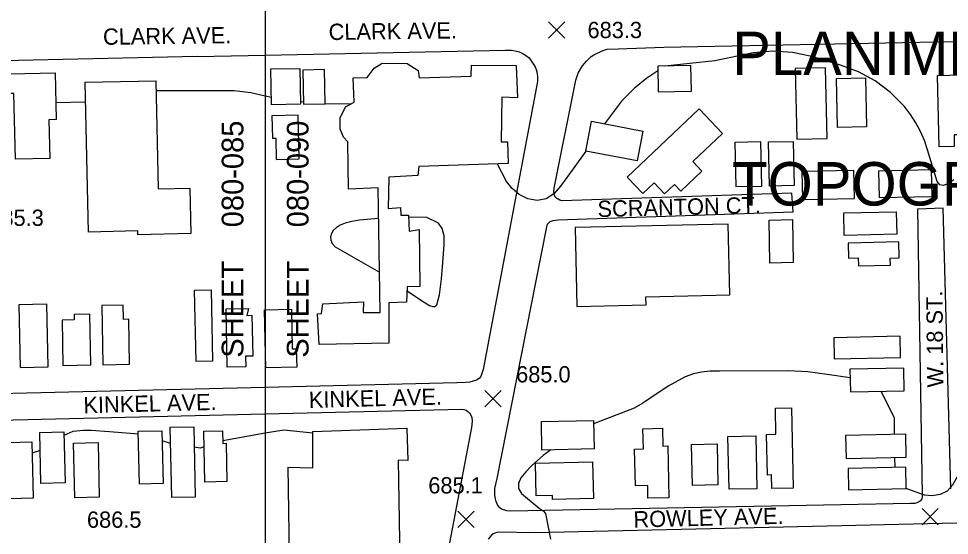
# Model space of a CAD drawing. Extents: x 79600 to 91800, y 75600 to 84400.
# Drawn here: x 84773 to 85630, y 78237 to 78712 of the extents above; entities that cross this region are included whole.
import ezdxf

# ---------------------------------------------------------------- set-up
doc = ezdxf.new("R2010")
doc.units = 0
for name, color, linetype in [('080-085$0$BLDG', 7, 'Continuous'), ('080-085$0$GRID', 7, 'Continuous'), ('080-085$0$INTER', 7, 'Continuous'), ('080-085$0$ROAD', 7, 'Continuous'), ('080-085$0$ROAD-NAME', 7, 'Continuous'), ('080-085$0$SPOTS', 7, 'Continuous'), ('080-085$0$TI_PLAN', 7, 'Continuous'), ('080-085$0$TI_SHEET', 7, 'Continuous'), ('080-085$0$TI_TOPO', 7, 'Continuous'), ('080-090$0$BLDG', 7, 'Continuous'), ('080-090$0$GRID', 7, 'Continuous'), ('080-090$0$INTER', 7, 'Continuous'), ('080-090$0$ROAD', 7, 'Continuous'), ('080-090$0$ROAD-NAME', 7, 'Continuous'), ('080-090$0$SPOTMARK', 7, 'Continuous'), ('080-090$0$SPOTS', 7, 'Continuous'), ('080-090$0$TI_SHEET', 7, 'Continuous')]:
    doc.layers.add(name, color=color, linetype=linetype)

# ---------------------------------------------------------------- blocks, each defined once
blk = doc.blocks.new('080-090$0$SPOTS')
at = {"layer": '080-090$0$SPOTMARK'}
for p, q in [((-0.5, -0.5), (0.5, 0.5)), ((-0.5, 0.5), (0.5, -0.5))]:
    blk.add_line(p, q, dxfattribs=at)

msp = doc.modelspace()

# ---------------------------------------------------------------- linework, layer by layer
at = {"layer": '080-085$0$BLDG'}
for p, q in [((84999.42, 78444.03), (85000, 78444.04)), ((85000, 78416.56), (84999.42, 78444.03))]:
    msp.add_line(p, q, dxfattribs=at)
for points in [[(84800.93, 78618.92), (84801.69, 78583.4), (84770, 78582.73), (84768.72, 78643.1), (84765.23, 78643.02), (84764.84, 78661.21), (84806.72, 78662.09), (84807.63, 78619.06)], [(84899.48, 78654.82), (84901.59, 78555.47), (84930.58, 78556.08), (84931.47, 78514.14), (84882.92, 78513.11), (84882.84, 78516.6), (84837.22, 78515.63), (84834.3, 78653.44)], [(84936.47, 78396.45), (84935.08, 78462.21), (84950.29, 78462.53), (84951.68, 78396.77)], [(84773.27, 78448.6), (84774.49, 78390.97), (84800.14, 78391.51), (84798.92, 78449.14)], [(84874.38, 78435.37), (84869.56, 78435.27), (84869.28, 78448.38), (84849.53, 78447.96), (84850.69, 78393.52), (84875.25, 78394.04)], [(84983.05, 78438.97), (84987.86, 78439.07), (84988.65, 78401.57), (84981.89, 78401.43), (84982.1, 78391.56), (84965.15, 78391.2), (84964.01, 78444.97), (84984.69, 78445.41)], [(84824.15, 78439.71), (84824.25, 78434.79), (84812.95, 78434.55), (84813.83, 78392.87), (84839.64, 78393.42), (84838.65, 78440.02)], [(84793.47, 78284.37), (84792.39, 78331.19), (84814.68, 78331.71), (84815.77, 78284.88)], [(84884.34, 78283.68), (84883.22, 78332.32), (84904.9, 78332.82), (84906.03, 78284.19)], [(84935.7, 78271.82), (84913.94, 78271.32), (84912.44, 78336.01), (84934.2, 78336.51)], [(84960.99, 78321.19), (84963.97, 78321.26), (84964.79, 78286.03), (84944.55, 78285.56), (84943.46, 78332.41), (84960.72, 78332.81)], [(84764.24, 78270.22), (84763.04, 78322.07), (84785.17, 78322.58), (84786.37, 78270.73)], [(84824.7, 78271.08), (84823.53, 78321.41), (84846.1, 78321.93), (84847.27, 78271.61)]]:
    msp.add_lwpolyline(points, close=True, dxfattribs=at)
at = {"layer": '080-085$0$GRID'}
msp.add_line((85000, 80000), (85000, 76000), dxfattribs=at)
at = {"layer": '080-085$0$INTER'}
for p, q in [((84834.69, 78635.03), (84807.3, 78634.5)), ((84912.79, 78321.17), (84905.12, 78323.52)), ((85000, 78330.72), (84960.94, 78323.43)), ((84792.77, 78314.53), (84785.41, 78312.08))]:
    msp.add_line(p, q, dxfattribs=at)
for points in [[(85000, 78640.69), (84986.98, 78643.63), (84971.62, 78645.59), (84899.68, 78645.49)], [(84883.28, 78329.77), (84856.68, 78331.78), (84839.69, 78332.97), (84832.62, 78333.12), (84823.06, 78332.05), (84814.76, 78328.39)], [(84943.8, 78317.91), (84940.04, 78316.7), (84934.64, 78317.59)]]:
    msp.add_lwpolyline(points, dxfattribs=at)
at = {"layer": '080-085$0$ROAD'}
msp.add_line((84937.29, 78676.99), (85000, 78678.32), dxfattribs=at)
for points in [[(85000, 78372.63), (84521.84, 78361.26), (84519.9, 78361.29), (84517.42, 78361.88), (84515.09, 78363.3), (84513.73, 78364.99), (84512.92, 78366.66), (84512.72, 78371.37), (84517.68, 78424.19), (84540.23, 78719.64)], [(84937.29, 78676.99), (84717.59, 78672.33), (84567.15, 78669.52), (84563, 78669.44), (84550.67, 78669.49), (84547.9, 78669.4), (84543.73, 78668.49), (84541.5, 78667.69), (84539.82, 78666.47), (84538.27, 78664.56), (84537.28, 78662.91), (84536.13, 78660.71), (84534.84, 78657.41), (84534.22, 78653.27)], [(84590.39, 78108.86), (84506.32, 78108.08), (84499.67, 78108.18), (84497.74, 78108.62), (84496.5, 78109.2), (84494.19, 78112.14), (84493.43, 78116.31), (84493.68, 78123.78), (84511.93, 78329.42), (84511.95, 78330.53), (84512.12, 78332.47), (84513.25, 78334.11), (84515.36, 78335.88), (84517.72, 78336.54), (84520.36, 78336.91), (84523.68, 78337), (85000, 78348.24)]]:
    msp.add_lwpolyline(points, dxfattribs=at)
at = {"layer": '080-090$0$BLDG'}
for points in [[(85005.89, 78632.66), (85005.19, 78665.69), (85031.9, 78666.25), (85032.6, 78633.23)], [(85113.82, 78413.51), (85049.69, 78412.16), (85048.32, 78440.41), (85051.92, 78440.64), (85053.16, 78449.48), (85090.45, 78451.4), (85090.43, 78441.71), (85105.81, 78441.61), (85104.1, 78556.16), (85076.81, 78555.19), (85076.09, 78598.69), (85072.14, 78603.04), (85069.21, 78610.43), (85069.23, 78620.81), (85073.95, 78630.71), (85081.91, 78635.16), (85081.15, 78657.46), (85094.03, 78657.96), (85100.26, 78666.31), (85107.81, 78671.04), (85130.93, 78670.82), (85141.07, 78664.16), (85141.94, 78657.5), (85189.74, 78659.12), (85190.04, 78669.09), (85231.3, 78668.87), (85232.37, 78639.22), (85217.97, 78639.85), (85217.34, 78598.6), (85223.15, 78598.51), (85223.68, 78578.56), (85141.52, 78575.8), (85140.56, 78567.79), (85113.81, 78566.26), (85113.37, 78537.18), (85124.6, 78538.12), (85125.04, 78531.19), (85132.11, 78531.08), (85132.71, 78516.39), (85141.87, 78517.91), (85142.32, 78465.56), (85130.82, 78465.32), (85130.32, 78451.06), (85113.97, 78450.35)], [(85361.88, 78644.7), (85392.5, 78645.19), (85392.13, 78668.76), (85361.5, 78668.27)], [(85517.43, 78601.58), (85516, 78666.75), (85488.08, 78666.14), (85489.51, 78600.97)], [(85055.4, 78633.6), (85054.74, 78665.06), (85034.8, 78664.64), (85035.47, 78633.17)], [(85527, 78611.83), (85526.02, 78656.84), (85552.78, 78657.43), (85553.77, 78612.41)], [(85634.41, 78604.98), (85634.64, 78594.25), (85620.65, 78593.95), (85619.21, 78659.68), (85641.38, 78660.16), (85642.59, 78605.16)], [(85006.23, 78622.57), (85006.67, 78601.99), (85009.87, 78602.06), (85010.28, 78582.48), (85031.32, 78582.92), (85030.47, 78623.08)], [(85347.83, 78551.07), (85358.16, 78560.87), (85367.86, 78550.65), (85376.9, 78559.23), (85382.69, 78553.13), (85402.3, 78571.75), (85393.91, 78580.6), (85421.12, 78606.42), (85399.72, 78628.97), (85333.52, 78566.15)], [(85342.72, 78581.14), (85295.31, 78590.04), (85300.46, 78617.49), (85347.88, 78608.58)], [(85433.76, 78557.17), (85432.86, 78598.37), (85456.08, 78598.88), (85456.98, 78557.68)], [(85464.31, 78557.82), (85463.42, 78598.5), (85486.14, 78598.99), (85487.03, 78558.32)], [(85494.79, 78545.46), (85542.65, 78546.51), (85542.09, 78572.26), (85494.23, 78571.21)], [(85565.37, 78547.27), (85614.25, 78548.34), (85613.71, 78572.86), (85564.83, 78571.79)], [(85533.31, 78512.53), (85532.86, 78533.16), (85581.17, 78534.22), (85581.62, 78513.59)], [(85287.12, 78447.26), (85350.82, 78448.65), (85350.66, 78456.06), (85427.79, 78457.75), (85426.37, 78522.81), (85285.53, 78519.73)], [(85485.53, 78527.09), (85486.39, 78487.48), (85464.86, 78487.01), (85464, 78526.62)], [(85537.24, 78491.66), (85546.11, 78491.85), (85546.27, 78484.5), (85575.77, 78485.14), (85575.63, 78491.63), (85583.73, 78491.81), (85583.41, 78506.5), (85536.93, 78505.48)], [(85524.15, 78399.01), (85585.21, 78400.35), (85584.78, 78419.77), (85523.73, 78418.43)], [(85539.02, 78368.49), (85588.56, 78369.57), (85588.1, 78390.44), (85538.56, 78389.36)], [(85466.72, 78279.56), (85466.45, 78292.14), (85462.59, 78292.06), (85461.78, 78329.49), (85470.39, 78329.67), (85469.87, 78353.48), (85484.73, 78353.8), (85486.35, 78279.99)], [(85254.96, 78315.03), (85254.39, 78341.23), (85302.43, 78342.28), (85303, 78316.08)], [(85136.61, 78165.97), (85051.25, 78162.71), (85048.92, 78200.14), (85022.72, 78198.47), (85021.08, 78299.31), (85044.06, 78298.81), (85043.88, 78332.05), (85130.34, 78335.15), (85131.41, 78305.36), (85122.55, 78305.64), (85124.31, 78194.83), (85134.14, 78194.54)], [(85352.27, 78282.46), (85340.91, 78282.21), (85340.18, 78315.92), (85348.3, 78316.1), (85347.89, 78334.72), (85366.02, 78335.12), (85366.38, 78318.71), (85370.79, 78318.81), (85371.83, 78271.09), (85352.53, 78270.67)], [(85427.28, 78278.95), (85426.22, 78327.52), (85451.78, 78328.08), (85452.85, 78279.51)], [(85534.95, 78307.15), (85590.38, 78308.37), (85589.91, 78329.58), (85534.48, 78328.37)], [(85393.56, 78282.57), (85392.73, 78320.27), (85416.21, 78320.78), (85417.03, 78283.08)], [(85302.25, 78270.49), (85264.77, 78269.67), (85264.69, 78273.29), (85249.56, 78272.96), (85248.9, 78302.96), (85301.51, 78304.11)], [(85537.26, 78278.41), (85590.46, 78279.57), (85590.02, 78299.34), (85536.82, 78298.17)]]:
    msp.add_lwpolyline(points, close=True, dxfattribs=at)
msp.add_lwpolyline([(85000, 78444.04), (85024.24, 78444.55), (85025.01, 78408.09), (85028.7, 78408.17), (85029.05, 78391.35), (85000.55, 78390.74), (85000, 78416.56)], dxfattribs=at)
at = {"layer": '080-090$0$GRID'}
msp.add_line((85000, 80000), (85000, 76000), dxfattribs=at)
at = {"layer": '080-090$0$INTER'}
for p, q in [((85005.75, 78639.27), (85000, 78640.69)), ((85035.43, 78635.15), (85032.55, 78635.51)), ((85078.81, 78633.42), (85055.4, 78633.65)), ((85148.93, 78529.14), (85132.18, 78529.18)), ((85580.24, 78299.12), (85579.9, 78308.14))]:
    msp.add_line(p, q, dxfattribs=at)
for points in [[(85634.18, 78563.63), (85628.62, 78560.05), (85624.41, 78558.47), (85621.32, 78559.17), (85618.9, 78562.23), (85609.99, 78591.2), (85607.06, 78599.72), (85603.52, 78608.12), (85599.26, 78616.22), (85594.28, 78623.92), (85588.65, 78631.17), (85575.77, 78644.07), (85561.67, 78654.71), (85546.54, 78663), (85529.88, 78669.19), (85503.47, 78677.25), (85485.59, 78680.89), (85467.58, 78681.93), (85449.52, 78680.52), (85414.24, 78673.23), (85368.18, 78668.38)], [(85361.57, 78664.05), (85351.42, 78657.17), (85340.12, 78648.09), (85328.08, 78636.08), (85312.43, 78615.24)], [(85295.45, 78590.02), (85283.67, 78573.77), (85277.98, 78565.8), (85272.14, 78557.8), (85265.88, 78550.89), (85258.74, 78546.23), (85250.5, 78544.73), (85241.9, 78546.17), (85233.93, 78550.06), (85227.38, 78555.79), (85222.34, 78562.21), (85214.03, 78578.23)], [(85130.69, 78461.6), (85144.07, 78452.5), (85151.49, 78448.09), (85154.34, 78447.02), (85156.48, 78447.07), (85158.08, 78448.63), (85160.44, 78457.77), (85162.3, 78472.51), (85163.74, 78487.57), (85164.93, 78503.99), (85164.76, 78512.17), (85163.15, 78519), (85159.72, 78523.68), (85148.93, 78529.14)], [(85104.52, 78528.11), (85086.97, 78526.48), (85079.71, 78525.35), (85073.67, 78523.83), (85068.95, 78521.93), (85065.37, 78519.65), (85062.76, 78517.03), (85061.09, 78514.15), (85060.32, 78511.15), (85060.49, 78508.11), (85061.82, 78505.08), (85064.59, 78502.07), (85105.25, 78478.64)], [(85538.74, 78381.4), (85517.61, 78384.69), (85499.79, 78386.94), (85482.03, 78388.08), (85418.38, 78387.48), (85409.76, 78387.49), (85401.88, 78386.75), (85394.42, 78385.07), (85386.95, 78382.32), (85371.15, 78373.75), (85347.88, 78358.04), (85339.84, 78353.45), (85302.5, 78339.08)], [(85579.63, 78329.36), (85579.64, 78344.27), (85567.29, 78369.1)], [(85043.89, 78330.69), (85017.1, 78333.37), (85000, 78330.72)], [(85263.14, 78315.21), (85255.89, 78309.93), (85245.64, 78300.94), (85239.95, 78295.09), (85235.46, 78289.36), (85233.22, 78284.36), (85233.44, 78279.8), (85236.13, 78275.21), (85252.33, 78261.71), (85256.01, 78259.06), (85258.21, 78256.7), (85262.74, 78233.18)], [(85708.2, 78308.24), (85715.67, 78301.25), (85722.35, 78293.04), (85727.09, 78284.52), (85728.08, 78281.19), (85727.92, 78278.67), (85726.47, 78276.93), (85723.64, 78275.97), (85713.94, 78276.7), (85678.16, 78288.59), (85663.24, 78293.26), (85649.65, 78296.86), (85645.1, 78297.56), (85641.82, 78296.83), (85636.36, 78288.83), (85632.88, 78282.66), (85628.07, 78277.3), (85621.61, 78274.13), (85614.25, 78273.03), (85607.06, 78273.48), (85590.45, 78279.78)]]:
    msp.add_lwpolyline(points, dxfattribs=at)
at = {"layer": '080-090$0$ROAD'}
for p, q in [((85367.27, 78685.75), (85858.06, 78695.52)), ((85000, 78678.32), (85220.99, 78683.01)), ((85220.99, 78683.01), (85226.81, 78682.92)), ((85226.81, 78682.92), (85230.4, 78682.45)), ((85310.3, 78682.33), (85314.9, 78683.92)), ((85314.9, 78683.92), (85325.15, 78684.32)), ((85325.15, 78684.32), (85367.27, 78685.75)), ((85230.4, 78682.45), (85233.99, 78681.57)), ((85233.99, 78681.57), (85236.74, 78680.28)), ((85236.74, 78680.28), (85239.89, 78678.43)), ((85239.89, 78678.43), (85243.04, 78675.89)), ((85243.04, 78675.89), (85246.83, 78670.43)), ((85295.89, 78672.72), (85300.25, 78677.09)), ((85300.25, 78677.09), (85302.63, 78678.71)), ((85302.63, 78678.71), (85310.3, 78682.33)), ((85246.83, 78670.43), (85248.59, 78667.49)), ((85248.59, 78667.49), (85249.66, 78665.12)), ((85288.38, 78661.9), (85292.23, 78668.49)), ((85292.23, 78668.49), (85295.89, 78672.72)), ((85249.66, 78665.12), (85250.32, 78663.04)), ((85250.32, 78663.04), (85250.81, 78658.6)), ((85250.81, 78658.6), (85250.88, 78654.16)), ((85286.21, 78655.28), (85288.38, 78661.9)), ((85250.88, 78654.16), (85200.83, 78389.05)), ((85266.12, 78556.02), (85286.21, 78655.28)), ((85265.94, 78553.26), (85266.12, 78556.02)), ((85266.04, 78550.35), (85265.94, 78553.26)), ((85266.84, 78548.67), (85266.04, 78550.35)), ((85267.66, 78547.55), (85266.84, 78548.67)), ((85268.75, 78546.57), (85267.66, 78547.55)), ((85269.98, 78545.86), (85268.75, 78546.57)), ((85271.35, 78544.87), (85269.98, 78545.86)), ((85485.13, 78551.27), (85273.15, 78544.28)), ((85486.11, 78534.23), (85485.13, 78551.27)), ((85273.15, 78544.28), (85271.35, 78544.87)), ((85624.37, 78537.5), (85600.82, 78536.76)), ((85631.34, 78279.27), (85624.37, 78537.5)), ((85269.41, 78526.75), (85486.11, 78534.23)), ((85600.82, 78536.76), (85605.08, 78273.85)), ((85259.18, 78519.02), (85259.94, 78522.88)), ((85259.94, 78522.88), (85262.33, 78525.2)), ((85262.33, 78525.2), (85265.25, 78526.4)), ((85265.25, 78526.4), (85269.41, 78526.75)), ((85213.69, 78289.01), (85259.18, 78519.02)), ((85200.83, 78389.05), (85198.65, 78382.71)), ((85176.54, 78376.82), (85000, 78372.63)), ((85184.72, 78377.11), (85176.54, 78376.82)), ((85188.6, 78377.6), (85184.72, 78377.11)), ((85194.58, 78379.31), (85188.6, 78377.6)), ((85197.1, 78380.94), (85194.58, 78379.31)), ((85198.65, 78382.71), (85197.1, 78380.94)), ((85000, 78348.24), (85181.02, 78352.52)), ((85181.02, 78352.52), (85182.95, 78352.35)), ((85182.95, 78352.35), (85185.02, 78351.63)), ((85185.02, 78351.63), (85186.66, 78350.49)), ((85186.66, 78350.49), (85188.3, 78348.94)), ((85188.3, 78348.94), (85189.25, 78347.82)), ((85189.25, 78347.82), (85190.32, 78344.9)), ((85190.54, 78341.71), (85190.04, 78335.9)), ((85190.32, 78344.9), (85190.54, 78341.71)), ((85190.04, 78335.9), (85151.66, 78136.24)), ((85211.47, 78279.62), (85213.69, 78289.01)), ((85211.52, 78273.67), (85211.47, 78279.62)), ((85212.02, 78270.06), (85211.52, 78273.67)), ((85605.06, 78272.05), (85604.61, 78270.12)), ((85605.08, 78273.85), (85605.06, 78272.05)), ((85212.81, 78267.69), (85212.02, 78270.06)), ((85213.87, 78264.77), (85212.81, 78267.69)), ((85216.18, 78261.83), (85213.87, 78264.77)), ((85594.3, 78265.85), (85225.97, 78258.77)), ((85598.32, 78265.93), (85594.3, 78265.85)), ((85600.26, 78266.45), (85598.32, 78265.93)), ((85601.8, 78267.12), (85600.26, 78266.45)), ((85603.48, 78268.34), (85601.8, 78267.12)), ((85604.61, 78270.12), (85603.48, 78268.34)), ((85217.82, 78260.55), (85216.18, 78261.83)), ((85222.51, 78259.24), (85217.82, 78260.55)), ((85225.97, 78258.77), (85222.51, 78259.24)), ((86134.56, 78259.9), (85517.67, 78244.87)), ((85210.14, 78237.96), (85208.32, 78236.6)), ((85213.48, 78239.29), (85210.14, 78237.96)), ((85214.46, 78239.56), (85213.48, 78239.29)), ((85248.65, 78239.03), (85214.46, 78239.56)), ((85517.67, 78244.87), (85248.65, 78239.03)), ((85208.32, 78236.6), (85205.35, 78232.91))]:
    msp.add_line(p, q, dxfattribs=at)

# ---------------------------------------------------------------- block references
at = {"layer": '080-090$0$SPOTMARK', "xscale": 15, "yscale": 15}
for p in [(85268.58, 78701.58), (85209.77, 78362.26), (85184.88, 78251.42), (85612.42, 78253.68)]:
    msp.add_blockref('080-090$0$SPOTS', p, dxfattribs=at)

# ---------------------------------------------------------------- texts
at = {"layer": '080-085$0$ROAD-NAME'}
for s, rotation, p in [('CLARK AVE.', 0.74364, (84850.79, 78687.83)), ('KINKEL AVE.', 1.44972, (84832.85, 78348.87))]:
    msp.add_text(s, height=15, rotation=rotation, dxfattribs=at).set_placement(p)
at = {"layer": '080-085$0$SPOTS'}
for s, p in [('685.3', (84746, 78521.27)), ('686.5', (84835.94, 78243.53))]:
    msp.add_text(s, height=15, dxfattribs=at).set_placement(p)
at = {"layer": '080-085$0$TI_PLAN'}
msp.add_text('PLANIMETRIC  MAP', height=40, dxfattribs=at).set_placement((85430, 78660))
at = {"layer": '080-085$0$TI_SHEET'}
for s, p in [('080-090', (85040, 78520)), ('SHEET', (85040, 78400))]:
    msp.add_text(s, height=20, rotation=90, dxfattribs=at).set_placement(p)
at = {"layer": '080-085$0$TI_TOPO'}
msp.add_text('TOPOGRAPHIC  MAP', height=40, dxfattribs=at).set_placement((85430, 78540))
at = {"layer": '080-090$0$ROAD-NAME'}
for s, rotation, p in [('CLARK AVE.', 0.74364, (85058.56, 78692.25)), ('SCRANTON CT.', 1.44972, (85306.26, 78529.35)), ('W. 18 ST.', 90.65918, (85624.74, 78372.69)), ('KINKEL AVE.', 1.44972, (85040.43, 78353.77)), ('ROWLEY AVE.', 1.44972, (85339.35, 78243.7))]:
    msp.add_text(s, height=15, rotation=rotation, dxfattribs=at).set_placement(p)
at = {"layer": '080-090$0$SPOTS'}
for s, p in [('683.3', (85296.88, 78694.02)), ('685.0', (85231.12, 78377.26)), ('685.1', (85150.27, 78275.1))]:
    msp.add_text(s, height=15, dxfattribs=at).set_placement(p)
at = {"layer": '080-090$0$TI_SHEET'}
for s, p in [('080-085', (84980, 78520)), ('SHEET', (84980, 78400))]:
    msp.add_text(s, height=20, rotation=90, dxfattribs=at).set_placement(p)

doc.saveas('drawing.dxf')
